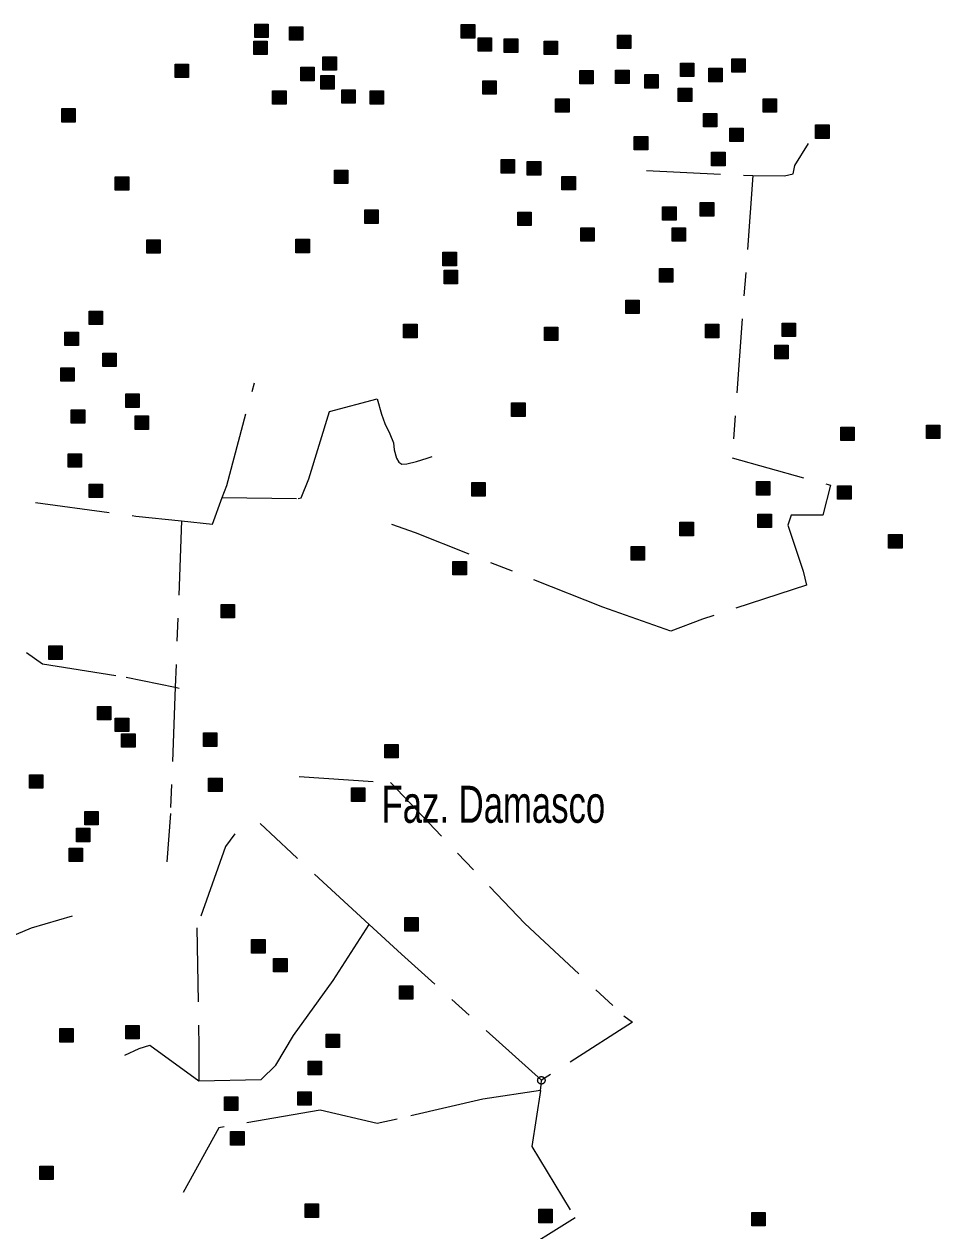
# Model space of a CAD drawing. Extents: x 445.4 to 500, y 8728.7 to 8784.
# Drawn here: x 472.02 to 475.98, y 8765.04 to 8770.24 of the extents above; entities that cross this region are included whole.
import ezdxf

# ---------------------------------------------------------------- set-up
doc = ezdxf.new("R2010")
doc.units = 0
doc.header["$LTSCALE"] = 0.064
doc.header["$PDMODE"] = 32
doc.header["$PDSIZE"] = 0.032
doc.linetypes.add('DOT_DASHED', pattern=[7.7, 5, -1.2, 0.3, -1.2])
doc.layers.add('2', color=7, linetype='Continuous', lineweight=25)
doc.layers.add('22', color=7, linetype='DOT_DASHED', lineweight=13)
doc.layers.add('61', color=7, linetype='Continuous')

msp = doc.modelspace()

# ---------------------------------------------------------------- hatches: boundary and pattern name
at = {"layer": '2'}
for points in [[(473.0194, 8770.2433), (473.0774, 8770.2433), (473.0774, 8770.1853), (473.0194, 8770.1853)], [(473.1687, 8770.232), (473.2267, 8770.232), (473.2267, 8770.174), (473.1687, 8770.174)], [(473.9108, 8770.2411), (473.9688, 8770.2411), (473.9688, 8770.1831), (473.9108, 8770.1831)], [(473.0148, 8770.1704), (473.0728, 8770.1704), (473.0728, 8770.1124), (473.0148, 8770.1124)], [(473.9832, 8770.184), (474.0412, 8770.184), (474.0412, 8770.126), (473.9832, 8770.126)], [(474.0963, 8770.1795), (474.1543, 8770.1795), (474.1543, 8770.1215), (474.0963, 8770.1215)], [(474.2682, 8770.1704), (474.3262, 8770.1704), (474.3262, 8770.1124), (474.2682, 8770.1124)], [(474.585, 8770.1958), (474.643, 8770.1958), (474.643, 8770.1378), (474.585, 8770.1378)], [(473.3135, 8770.1025), (473.3715, 8770.1025), (473.3715, 8770.0445), (473.3135, 8770.0445)], [(472.6754, 8770.0708), (472.7334, 8770.0708), (472.7334, 8770.0128), (472.6754, 8770.0128)], [(473.2184, 8770.0572), (473.2764, 8770.0572), (473.2764, 8769.9992), (473.2184, 8769.9992)], [(474.577, 8770.0449), (474.635, 8770.0449), (474.635, 8769.9869), (474.577, 8769.9869)], [(474.8565, 8770.0754), (474.9145, 8770.0754), (474.9145, 8770.0174), (474.8565, 8770.0174)], [(474.9787, 8770.0527), (475.0367, 8770.0527), (475.0367, 8769.9947), (474.9787, 8769.9947)], [(475.0782, 8770.0935), (475.1362, 8770.0935), (475.1362, 8770.0355), (475.0782, 8770.0355)], [(473.3044, 8770.021), (473.3624, 8770.021), (473.3624, 8769.963), (473.3044, 8769.963)], [(474.0033, 8769.9991), (474.0613, 8769.9991), (474.0613, 8769.9411), (474.0033, 8769.9411)], [(474.4221, 8770.0437), (474.4801, 8770.0437), (474.4801, 8769.9857), (474.4221, 8769.9857)], [(474.7026, 8770.0256), (474.7606, 8770.0256), (474.7606, 8769.9676), (474.7026, 8769.9676)], [(473.0963, 8769.9559), (473.1543, 8769.9559), (473.1543, 8769.8979), (473.0963, 8769.8979)], [(473.3949, 8769.9604), (473.4529, 8769.9604), (473.4529, 8769.9024), (473.3949, 8769.9024)], [(473.5171, 8769.9559), (473.5751, 8769.9559), (473.5751, 8769.8979), (473.5171, 8769.8979)], [(474.8474, 8769.9667), (474.9054, 8769.9667), (474.9054, 8769.9087), (474.8474, 8769.9087)], [(474.318, 8769.9214), (474.376, 8769.9214), (474.376, 8769.8634), (474.318, 8769.8634)], [(475.214, 8769.9214), (475.272, 8769.9214), (475.272, 8769.8634), (475.214, 8769.8634)], [(472.1867, 8769.8787), (472.2447, 8769.8787), (472.2447, 8769.8207), (472.1867, 8769.8207)], [(474.956, 8769.858), (475.014, 8769.858), (475.014, 8769.8), (474.956, 8769.8)], [(475.0692, 8769.7947), (475.1272, 8769.7947), (475.1272, 8769.7367), (475.0692, 8769.7367)], [(475.4402, 8769.8082), (475.4982, 8769.8082), (475.4982, 8769.7502), (475.4402, 8769.7502)], [(474.6574, 8769.7584), (474.7154, 8769.7584), (474.7154, 8769.7004), (474.6574, 8769.7004)], [(474.9912, 8769.6904), (475.0492, 8769.6904), (475.0492, 8769.6324), (474.9912, 8769.6324)], [(474.0827, 8769.6588), (474.1407, 8769.6588), (474.1407, 8769.6008), (474.0827, 8769.6008)], [(474.1958, 8769.6498), (474.2538, 8769.6498), (474.2538, 8769.5918), (474.1958, 8769.5918)], [(472.4175, 8769.5845), (472.4755, 8769.5845), (472.4755, 8769.5265), (472.4175, 8769.5265)], [(473.3632, 8769.6136), (473.4212, 8769.6136), (473.4212, 8769.5556), (473.3632, 8769.5556)], [(474.3452, 8769.5864), (474.4032, 8769.5864), (474.4032, 8769.5284), (474.3452, 8769.5284)], [(474.9425, 8769.4732), (475.0005, 8769.4732), (475.0005, 8769.4152), (474.9425, 8769.4152)], [(473.4945, 8769.4415), (473.5525, 8769.4415), (473.5525, 8769.3835), (473.4945, 8769.3835)], [(474.1551, 8769.4325), (474.2131, 8769.4325), (474.2131, 8769.3745), (474.1551, 8769.3745)], [(474.7796, 8769.4551), (474.8376, 8769.4551), (474.8376, 8769.3971), (474.7796, 8769.3971)], [(473.1971, 8769.3147), (473.2551, 8769.3147), (473.2551, 8769.2567), (473.1971, 8769.2567)], [(474.4266, 8769.3646), (474.4846, 8769.3646), (474.4846, 8769.3066), (474.4266, 8769.3066)], [(474.8203, 8769.3646), (474.8783, 8769.3646), (474.8783, 8769.3066), (474.8203, 8769.3066)], [(472.5532, 8769.3128), (472.6112, 8769.3128), (472.6112, 8769.2548), (472.5532, 8769.2548)], [(473.8315, 8769.2587), (473.8895, 8769.2587), (473.8895, 8769.2007), (473.8315, 8769.2007)], [(473.8369, 8769.1811), (473.8949, 8769.1811), (473.8949, 8769.1231), (473.8369, 8769.1231)], [(474.766, 8769.188), (474.824, 8769.188), (474.824, 8769.13), (474.766, 8769.13)], [(472.3043, 8769.0049), (472.3623, 8769.0049), (472.3623, 8768.9469), (472.3043, 8768.9469)], [(474.6212, 8769.0522), (474.6792, 8769.0522), (474.6792, 8768.9942), (474.6212, 8768.9942)], [(475.2954, 8768.9526), (475.3534, 8768.9526), (475.3534, 8768.8946), (475.2954, 8768.8946)], [(472.2003, 8768.9144), (472.2583, 8768.9144), (472.2583, 8768.8564), (472.2003, 8768.8564)], [(473.6619, 8768.948), (473.7199, 8768.948), (473.7199, 8768.89), (473.6619, 8768.89)], [(474.2693, 8768.9358), (474.3273, 8768.9358), (474.3273, 8768.8778), (474.2693, 8768.8778)], [(474.9651, 8768.948), (475.0231, 8768.948), (475.0231, 8768.89), (474.9651, 8768.89)], [(475.2637, 8768.8575), (475.3217, 8768.8575), (475.3217, 8768.7995), (475.2637, 8768.7995)], [(472.3632, 8768.8238), (472.4212, 8768.8238), (472.4212, 8768.7658), (472.3632, 8768.7658)], [(472.1822, 8768.7605), (472.2402, 8768.7605), (472.2402, 8768.7025), (472.1822, 8768.7025)], [(472.4627, 8768.6473), (472.5207, 8768.6473), (472.5207, 8768.5893), (472.4627, 8768.5893)], [(474.128, 8768.6085), (474.186, 8768.6085), (474.186, 8768.5505), (474.128, 8768.5505)], [(472.2274, 8768.5794), (472.2854, 8768.5794), (472.2854, 8768.5214), (472.2274, 8768.5214)], [(472.5034, 8768.5522), (472.5614, 8768.5522), (472.5614, 8768.4942), (472.5034, 8768.4942)], [(475.5488, 8768.5043), (475.6068, 8768.5043), (475.6068, 8768.4463), (475.5488, 8768.4463)], [(475.9184, 8768.5127), (475.9764, 8768.5127), (475.9764, 8768.4547), (475.9184, 8768.4547)], [(472.2138, 8768.3892), (472.2718, 8768.3892), (472.2718, 8768.3312), (472.2138, 8768.3312)], [(472.3043, 8768.2579), (472.3623, 8768.2579), (472.3623, 8768.1999), (472.3043, 8768.1999)], [(473.956, 8768.2644), (474.014, 8768.2644), (474.014, 8768.2064), (473.956, 8768.2064)], [(475.185, 8768.2688), (475.243, 8768.2688), (475.243, 8768.2108), (475.185, 8768.2108)], [(475.5352, 8768.2508), (475.5932, 8768.2508), (475.5932, 8768.1928), (475.5352, 8768.1928)], [(475.1913, 8768.1286), (475.2493, 8768.1286), (475.2493, 8768.0706), (475.1913, 8768.0706)], [(474.8544, 8768.0934), (474.9124, 8768.0934), (474.9124, 8768.0354), (474.8544, 8768.0354)], [(475.755, 8768.04), (475.813, 8768.04), (475.813, 8767.982), (475.755, 8767.982)], [(474.6438, 8767.9882), (474.7018, 8767.9882), (474.7018, 8767.9302), (474.6438, 8767.9302)], [(473.8746, 8767.9248), (473.9326, 8767.9248), (473.9326, 8767.8668), (473.8746, 8767.8668)], [(472.8745, 8767.7392), (472.9325, 8767.7392), (472.9325, 8767.6812), (472.8745, 8767.6812)], [(472.1299, 8767.5598), (472.1879, 8767.5598), (472.1879, 8767.5018), (472.1299, 8767.5018)], [(472.3405, 8767.2981), (472.3985, 8767.2981), (472.3985, 8767.2401), (472.3405, 8767.2401)], [(472.4175, 8767.2483), (472.4755, 8767.2483), (472.4755, 8767.1903), (472.4175, 8767.1903)], [(472.4446, 8767.1804), (472.5026, 8767.1804), (472.5026, 8767.1224), (472.4446, 8767.1224)], [(472.7976, 8767.1841), (472.8556, 8767.1841), (472.8556, 8767.1261), (472.7976, 8767.1261)], [(473.5804, 8767.1343), (473.6384, 8767.1343), (473.6384, 8767.0763), (473.5804, 8767.0763)], [(472.0464, 8767.0038), (472.1044, 8767.0038), (472.1044, 8766.9458), (472.0464, 8766.9458)], [(472.8202, 8766.9894), (472.8782, 8766.9894), (472.8782, 8766.9314), (472.8202, 8766.9314)], [(473.4371, 8766.9469), (473.4951, 8766.9469), (473.4951, 8766.8889), (473.4371, 8766.8889)], [(472.2862, 8766.8453), (472.3442, 8766.8453), (472.3442, 8766.7873), (472.2862, 8766.7873)], [(472.25, 8766.7729), (472.308, 8766.7729), (472.308, 8766.7149), (472.25, 8766.7149)], [(472.2184, 8766.6869), (472.2764, 8766.6869), (472.2764, 8766.6289), (472.2184, 8766.6289)], [(473.6664, 8766.3873), (473.7244, 8766.3873), (473.7244, 8766.3293), (473.6664, 8766.3293)], [(473.0058, 8766.2922), (473.0638, 8766.2922), (473.0638, 8766.2342), (473.0058, 8766.2342)], [(473.1008, 8766.2107), (473.1588, 8766.2107), (473.1588, 8766.1527), (473.1008, 8766.1527)], [(473.6438, 8766.093), (473.7018, 8766.093), (473.7018, 8766.035), (473.6438, 8766.035)], [(472.1776, 8765.9082), (472.2356, 8765.9082), (472.2356, 8765.8502), (472.1776, 8765.8502)], [(472.4627, 8765.9217), (472.5207, 8765.9217), (472.5207, 8765.8637), (472.4627, 8765.8637)], [(473.327, 8765.8847), (473.385, 8765.8847), (473.385, 8765.8267), (473.327, 8765.8267)], [(473.2501, 8765.767), (473.3081, 8765.767), (473.3081, 8765.709), (473.2501, 8765.709)], [(473.2049, 8765.6357), (473.2629, 8765.6357), (473.2629, 8765.5777), (473.2049, 8765.5777)], [(472.8881, 8765.6131), (472.9461, 8765.6131), (472.9461, 8765.5551), (472.8881, 8765.5551)], [(472.9153, 8765.4637), (472.9733, 8765.4637), (472.9733, 8765.4057), (472.9153, 8765.4057)], [(472.0917, 8765.3151), (472.1497, 8765.3151), (472.1497, 8765.2571), (472.0917, 8765.2571)], [(473.2365, 8765.1513), (473.2945, 8765.1513), (473.2945, 8765.0933), (473.2365, 8765.0933)], [(474.2456, 8765.1286), (474.3036, 8765.1286), (474.3036, 8765.0706), (474.2456, 8765.0706)], [(475.1642, 8765.1151), (475.2222, 8765.1151), (475.2222, 8765.0571), (475.1642, 8765.0571)]]:
    msp.add_hatch(color=256, dxfattribs=at).paths.add_polyline_path(points)

# ---------------------------------------------------------------- linework, layer by layer
for points in [[(473.0194, 8770.2433), (473.0774, 8770.2433), (473.0774, 8770.1853), (473.0194, 8770.1853)], [(473.1687, 8770.232), (473.2267, 8770.232), (473.2267, 8770.174), (473.1687, 8770.174)], [(473.9108, 8770.2411), (473.9688, 8770.2411), (473.9688, 8770.1831), (473.9108, 8770.1831)], [(473.0148, 8770.1704), (473.0728, 8770.1704), (473.0728, 8770.1124), (473.0148, 8770.1124)], [(473.9832, 8770.184), (474.0412, 8770.184), (474.0412, 8770.126), (473.9832, 8770.126)], [(474.0963, 8770.1795), (474.1543, 8770.1795), (474.1543, 8770.1215), (474.0963, 8770.1215)], [(474.2682, 8770.1704), (474.3262, 8770.1704), (474.3262, 8770.1124), (474.2682, 8770.1124)], [(474.585, 8770.1958), (474.643, 8770.1958), (474.643, 8770.1378), (474.585, 8770.1378)], [(473.3135, 8770.1025), (473.3715, 8770.1025), (473.3715, 8770.0445), (473.3135, 8770.0445)], [(472.6754, 8770.0708), (472.7334, 8770.0708), (472.7334, 8770.0128), (472.6754, 8770.0128)], [(473.2184, 8770.0572), (473.2764, 8770.0572), (473.2764, 8769.9992), (473.2184, 8769.9992)], [(474.577, 8770.0449), (474.635, 8770.0449), (474.635, 8769.9869), (474.577, 8769.9869)], [(474.8565, 8770.0754), (474.9145, 8770.0754), (474.9145, 8770.0174), (474.8565, 8770.0174)], [(474.9787, 8770.0527), (475.0367, 8770.0527), (475.0367, 8769.9947), (474.9787, 8769.9947)], [(475.0782, 8770.0935), (475.1362, 8770.0935), (475.1362, 8770.0355), (475.0782, 8770.0355)], [(473.3044, 8770.021), (473.3624, 8770.021), (473.3624, 8769.963), (473.3044, 8769.963)], [(474.0033, 8769.9991), (474.0613, 8769.9991), (474.0613, 8769.9411), (474.0033, 8769.9411)], [(474.4221, 8770.0437), (474.4801, 8770.0437), (474.4801, 8769.9857), (474.4221, 8769.9857)], [(474.7026, 8770.0256), (474.7606, 8770.0256), (474.7606, 8769.9676), (474.7026, 8769.9676)], [(473.0963, 8769.9559), (473.1543, 8769.9559), (473.1543, 8769.8979), (473.0963, 8769.8979)], [(473.3949, 8769.9604), (473.4529, 8769.9604), (473.4529, 8769.9024), (473.3949, 8769.9024)], [(473.5171, 8769.9559), (473.5751, 8769.9559), (473.5751, 8769.8979), (473.5171, 8769.8979)], [(474.8474, 8769.9667), (474.9054, 8769.9667), (474.9054, 8769.9087), (474.8474, 8769.9087)], [(474.318, 8769.9214), (474.376, 8769.9214), (474.376, 8769.8634), (474.318, 8769.8634)], [(475.214, 8769.9214), (475.272, 8769.9214), (475.272, 8769.8634), (475.214, 8769.8634)], [(472.1867, 8769.8787), (472.2447, 8769.8787), (472.2447, 8769.8207), (472.1867, 8769.8207)], [(474.956, 8769.858), (475.014, 8769.858), (475.014, 8769.8), (474.956, 8769.8)], [(475.0692, 8769.7947), (475.1272, 8769.7947), (475.1272, 8769.7367), (475.0692, 8769.7367)], [(475.4402, 8769.8082), (475.4982, 8769.8082), (475.4982, 8769.7502), (475.4402, 8769.7502)], [(474.6574, 8769.7584), (474.7154, 8769.7584), (474.7154, 8769.7004), (474.6574, 8769.7004)], [(474.9912, 8769.6904), (475.0492, 8769.6904), (475.0492, 8769.6324), (474.9912, 8769.6324)], [(474.0827, 8769.6588), (474.1407, 8769.6588), (474.1407, 8769.6008), (474.0827, 8769.6008)], [(474.1958, 8769.6498), (474.2538, 8769.6498), (474.2538, 8769.5918), (474.1958, 8769.5918)], [(472.4175, 8769.5845), (472.4755, 8769.5845), (472.4755, 8769.5265), (472.4175, 8769.5265)], [(473.3632, 8769.6136), (473.4212, 8769.6136), (473.4212, 8769.5556), (473.3632, 8769.5556)], [(474.3452, 8769.5864), (474.4032, 8769.5864), (474.4032, 8769.5284), (474.3452, 8769.5284)], [(474.9425, 8769.4732), (475.0005, 8769.4732), (475.0005, 8769.4152), (474.9425, 8769.4152)], [(473.4945, 8769.4415), (473.5525, 8769.4415), (473.5525, 8769.3835), (473.4945, 8769.3835)], [(474.1551, 8769.4325), (474.2131, 8769.4325), (474.2131, 8769.3745), (474.1551, 8769.3745)], [(474.7796, 8769.4551), (474.8376, 8769.4551), (474.8376, 8769.3971), (474.7796, 8769.3971)], [(473.1971, 8769.3147), (473.2551, 8769.3147), (473.2551, 8769.2567), (473.1971, 8769.2567)], [(474.4266, 8769.3646), (474.4846, 8769.3646), (474.4846, 8769.3066), (474.4266, 8769.3066)], [(474.8203, 8769.3646), (474.8783, 8769.3646), (474.8783, 8769.3066), (474.8203, 8769.3066)], [(472.5532, 8769.3128), (472.6112, 8769.3128), (472.6112, 8769.2548), (472.5532, 8769.2548)], [(473.8315, 8769.2587), (473.8895, 8769.2587), (473.8895, 8769.2007), (473.8315, 8769.2007)], [(473.8369, 8769.1811), (473.8949, 8769.1811), (473.8949, 8769.1231), (473.8369, 8769.1231)], [(474.766, 8769.188), (474.824, 8769.188), (474.824, 8769.13), (474.766, 8769.13)], [(472.3043, 8769.0049), (472.3623, 8769.0049), (472.3623, 8768.9469), (472.3043, 8768.9469)], [(474.6212, 8769.0522), (474.6792, 8769.0522), (474.6792, 8768.9942), (474.6212, 8768.9942)], [(475.2954, 8768.9526), (475.3534, 8768.9526), (475.3534, 8768.8946), (475.2954, 8768.8946)], [(472.2003, 8768.9144), (472.2583, 8768.9144), (472.2583, 8768.8564), (472.2003, 8768.8564)], [(473.6619, 8768.948), (473.7199, 8768.948), (473.7199, 8768.89), (473.6619, 8768.89)], [(474.2693, 8768.9358), (474.3273, 8768.9358), (474.3273, 8768.8778), (474.2693, 8768.8778)], [(474.9651, 8768.948), (475.0231, 8768.948), (475.0231, 8768.89), (474.9651, 8768.89)], [(475.2637, 8768.8575), (475.3217, 8768.8575), (475.3217, 8768.7995), (475.2637, 8768.7995)], [(472.3632, 8768.8238), (472.4212, 8768.8238), (472.4212, 8768.7658), (472.3632, 8768.7658)], [(472.1822, 8768.7605), (472.2402, 8768.7605), (472.2402, 8768.7025), (472.1822, 8768.7025)], [(472.4627, 8768.6473), (472.5207, 8768.6473), (472.5207, 8768.5893), (472.4627, 8768.5893)], [(474.128, 8768.6085), (474.186, 8768.6085), (474.186, 8768.5505), (474.128, 8768.5505)], [(472.2274, 8768.5794), (472.2854, 8768.5794), (472.2854, 8768.5214), (472.2274, 8768.5214)], [(472.5034, 8768.5522), (472.5614, 8768.5522), (472.5614, 8768.4942), (472.5034, 8768.4942)], [(475.5488, 8768.5043), (475.6068, 8768.5043), (475.6068, 8768.4463), (475.5488, 8768.4463)], [(475.9184, 8768.5127), (475.9764, 8768.5127), (475.9764, 8768.4547), (475.9184, 8768.4547)], [(472.2138, 8768.3892), (472.2718, 8768.3892), (472.2718, 8768.3312), (472.2138, 8768.3312)], [(472.3043, 8768.2579), (472.3623, 8768.2579), (472.3623, 8768.1999), (472.3043, 8768.1999)], [(473.956, 8768.2644), (474.014, 8768.2644), (474.014, 8768.2064), (473.956, 8768.2064)], [(475.185, 8768.2688), (475.243, 8768.2688), (475.243, 8768.2108), (475.185, 8768.2108)], [(475.5352, 8768.2508), (475.5932, 8768.2508), (475.5932, 8768.1928), (475.5352, 8768.1928)], [(475.1913, 8768.1286), (475.2493, 8768.1286), (475.2493, 8768.0706), (475.1913, 8768.0706)], [(474.8544, 8768.0934), (474.9124, 8768.0934), (474.9124, 8768.0354), (474.8544, 8768.0354)], [(475.755, 8768.04), (475.813, 8768.04), (475.813, 8767.982), (475.755, 8767.982)], [(474.6438, 8767.9882), (474.7018, 8767.9882), (474.7018, 8767.9302), (474.6438, 8767.9302)], [(473.8746, 8767.9248), (473.9326, 8767.9248), (473.9326, 8767.8668), (473.8746, 8767.8668)], [(472.8745, 8767.7392), (472.9325, 8767.7392), (472.9325, 8767.6812), (472.8745, 8767.6812)], [(472.1299, 8767.5598), (472.1879, 8767.5598), (472.1879, 8767.5018), (472.1299, 8767.5018)], [(472.3405, 8767.2981), (472.3985, 8767.2981), (472.3985, 8767.2401), (472.3405, 8767.2401)], [(472.4175, 8767.2483), (472.4755, 8767.2483), (472.4755, 8767.1903), (472.4175, 8767.1903)], [(472.4446, 8767.1804), (472.5026, 8767.1804), (472.5026, 8767.1224), (472.4446, 8767.1224)], [(472.7976, 8767.1841), (472.8556, 8767.1841), (472.8556, 8767.1261), (472.7976, 8767.1261)], [(473.5804, 8767.1343), (473.6384, 8767.1343), (473.6384, 8767.0763), (473.5804, 8767.0763)], [(472.0464, 8767.0038), (472.1044, 8767.0038), (472.1044, 8766.9458), (472.0464, 8766.9458)], [(472.8202, 8766.9894), (472.8782, 8766.9894), (472.8782, 8766.9314), (472.8202, 8766.9314)], [(473.4371, 8766.9469), (473.4951, 8766.9469), (473.4951, 8766.8889), (473.4371, 8766.8889)], [(472.2862, 8766.8453), (472.3442, 8766.8453), (472.3442, 8766.7873), (472.2862, 8766.7873)], [(472.25, 8766.7729), (472.308, 8766.7729), (472.308, 8766.7149), (472.25, 8766.7149)], [(472.2184, 8766.6869), (472.2764, 8766.6869), (472.2764, 8766.6289), (472.2184, 8766.6289)], [(473.6664, 8766.3873), (473.7244, 8766.3873), (473.7244, 8766.3293), (473.6664, 8766.3293)], [(473.0058, 8766.2922), (473.0638, 8766.2922), (473.0638, 8766.2342), (473.0058, 8766.2342)], [(473.1008, 8766.2107), (473.1588, 8766.2107), (473.1588, 8766.1527), (473.1008, 8766.1527)], [(473.6438, 8766.093), (473.7018, 8766.093), (473.7018, 8766.035), (473.6438, 8766.035)], [(472.1776, 8765.9082), (472.2356, 8765.9082), (472.2356, 8765.8502), (472.1776, 8765.8502)], [(472.4627, 8765.9217), (472.5207, 8765.9217), (472.5207, 8765.8637), (472.4627, 8765.8637)], [(473.327, 8765.8847), (473.385, 8765.8847), (473.385, 8765.8267), (473.327, 8765.8267)], [(473.2501, 8765.767), (473.3081, 8765.767), (473.3081, 8765.709), (473.2501, 8765.709)], [(473.2049, 8765.6357), (473.2629, 8765.6357), (473.2629, 8765.5777), (473.2049, 8765.5777)], [(472.8881, 8765.6131), (472.9461, 8765.6131), (472.9461, 8765.5551), (472.8881, 8765.5551)], [(472.9153, 8765.4637), (472.9733, 8765.4637), (472.9733, 8765.4057), (472.9153, 8765.4057)], [(472.0917, 8765.3151), (472.1497, 8765.3151), (472.1497, 8765.2571), (472.0917, 8765.2571)], [(473.2365, 8765.1513), (473.2945, 8765.1513), (473.2945, 8765.0933), (473.2365, 8765.0933)], [(474.2456, 8765.1286), (474.3036, 8765.1286), (474.3036, 8765.0706), (474.2456, 8765.0706)], [(475.1642, 8765.1151), (475.2222, 8765.1151), (475.2222, 8765.0571), (475.1642, 8765.0571)]]:
    msp.add_lwpolyline(points, close=True, dxfattribs=at)
at = {"layer": '22'}
for p, q in [((474.7099, 8769.6109), (475.169, 8769.5899)), ((472.7035, 8768.0993), (472.6759, 8767.3814))]:
    msp.add_line(p, q, dxfattribs=at)
for points in [[(475.169, 8769.5899), (475.3053, 8769.5889), (475.3429, 8769.5968), (475.3509, 8769.6327), (475.4092, 8769.7276)], [(475.169, 8769.5899), (475.0797, 8768.371), (475.505, 8768.253), (475.4714, 8768.1234), (475.3343, 8768.1234), (475.3202, 8768.0809), (475.3863, 8767.8827), (475.4005, 8767.8213), (474.9516, 8767.675), (474.8145, 8767.6231), (474.5216, 8767.727), (473.7135, 8768.0479), (473.6117, 8768.0835)], [(472.8794, 8768.2006), (472.8983, 8768.2518), (473.0176, 8768.6946)], [(472.8794, 8768.2006), (473.2061, 8768.1958), (473.2197, 8768.1985), (473.2525, 8768.2803), (473.3426, 8768.5721), (473.5474, 8768.6266)], [(473.5474, 8768.6266), (473.5671, 8768.5604), (473.5801, 8768.5201), (473.6028, 8768.4746), (473.6184, 8768.4363), (473.621, 8768.4065), (473.6307, 8768.3701), (473.6405, 8768.3525), (473.6548, 8768.3441), (473.6762, 8768.3461), (473.7177, 8768.3551), (473.7632, 8768.3694), (473.7856, 8768.3771)], [(472.0734, 8768.1783), (472.506, 8768.1203), (472.7035, 8768.0993)], [(472.7035, 8768.0993), (472.8368, 8768.0852), (472.8794, 8768.2006)], [(472.034, 8767.5311), (472.1039, 8767.4822), (472.4649, 8767.4253), (472.6759, 8767.3814), (472.693, 8767.3778)], [(472.6759, 8767.3814), (472.655, 8766.8369), (472.64, 8766.6276)], [(473.211, 8766.9962), (473.6051, 8766.9698), (474.1847, 8766.3625), (474.6122, 8765.964), (474.6502, 8765.9355), (474.2564, 8765.685)], [(473.5134, 8766.3575), (473.1775, 8766.6661), (473.0431, 8766.7933)], [(472.9328, 8766.7494), (472.8925, 8766.6946), (472.769, 8766.3435), (472.7785, 8765.8311), (472.7778, 8765.6825)], [(471.4769, 8766.5703), (471.5611, 8766.4353), (471.6478, 8766.1917), (471.8284, 8766.2486), (472.0564, 8766.3435), (472.2334, 8766.3944)], [(472.7778, 8765.6825), (473.0466, 8765.6885), (473.1099, 8765.7503), (473.187, 8765.8786), (473.3581, 8766.1158), (473.5134, 8766.3575)], [(474.2564, 8765.685), (473.6526, 8766.2297), (473.5134, 8766.3575)], [(472.4585, 8765.7932), (472.5205, 8765.8222), (472.5671, 8765.8372), (472.7778, 8765.6825)], [(474.2531, 8765.6408), (474.2557, 8765.6662), (474.2564, 8765.685)], [(474.2531, 8765.6408), (474.0042, 8765.6034), (473.6336, 8765.518), (473.5481, 8765.499), (473.3011, 8765.5559), (472.864, 8765.48), (472.7106, 8765.201)], [(474.2531, 8765.6408), (474.2155, 8765.3995), (474.4016, 8765.0911), (474.1205, 8764.9155), (473.939, 8764.815)]]:
    msp.add_lwpolyline(points, dxfattribs=at)
msp.add_point((474.2564, 8765.685), dxfattribs=at)

# ---------------------------------------------------------------- texts
at = {"layer": '61', "width": 0.7}
msp.add_text('Faz. Damasco', height=0.16, dxfattribs=at).set_placement((473.5665, 8766.7964))

doc.saveas('drawing.dxf')
